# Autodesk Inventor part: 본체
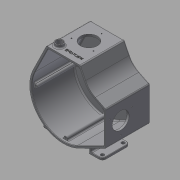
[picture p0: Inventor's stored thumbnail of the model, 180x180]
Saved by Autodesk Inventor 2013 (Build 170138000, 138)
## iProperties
Created: 2017-05
Part Number: 본체
Material: 일반
Document SubType Name: Modeling
Designer: mduedu
Density: 1 g/cm^3
Author: mduedu
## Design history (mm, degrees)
sketch "스케치1"
  geometry: L1 (-71.801, 35.28)-(-40, 100); L2 (-40, 100)-(40, 100); L3 (40, 100)-(59.768, 59.768); L4 (59.768, 59.768)-(100, 40); L5 (100, 40)-(100, -40); L6 (100, -40)-(35.28, -71.801); A1 r 80 centre (0, 0) between (-71.801, 35.28) and (35.28, -71.801); 3 further points
  constraints: 12 end point, 4 tangent, 2 midpoint, 2 point on circle, 1 centre point, 1 coincident, 1 horizontal, 1 horizontal alignment, 1 perpendicular, 1 vertical alignment
  dimensions: "d0" = 160 diameter of A1; "d2" = 100 distance from line of L2 point (0, 0); "d3" = 100 distance from line of L5 point (0, 0); "d4" = 80 distance of L1.end L2.end; "d5" = 80 distance of L4.end L5.end
extrude "돌출1" new body sketch "스케치1" distance "d6" = 5; taper "d7" = 0 deg
fillet "모깎기1" dims "d8" = 50
sketch "스케치2"
  geometry: C1 r 22 at (0, 0); 1 further point
  constraints: 1 centre point, 1 coincident
  dimensions: "d9" = 44 diameter of C1
extrude "돌출2" join sketch "스케치2" distance "d10" = 22.5; taper "d11" = 0 deg
sketch "스케치3"
  geometry: C1 r 18.5 at (0, 0); 1 further point
  constraints: 1 centre point, 1 coincident
  dimensions: "d12" = 37 diameter of C1
extrude "돌출3" cut sketch "스케치3" distance "d13" = 9; taper "d14" = 0 deg
fillet "모깎기2" dims "d15" = 3
sketch "스케치4"
  geometry: L1 (35.28, -71.801)-(100, -40) reference; L2 (100, -40)-(100, 40) reference; L3 (100, 40)-(75.073, 52.248) reference; L4 (52.248, 75.073)-(40, 100) reference; L5 (40, 100)-(-40, 100) reference; L6 (-40, 100)-(-71.801, 35.28) reference; L7 (-36.886, 95)-(36.886, 95); L8 (36.886, 95)-(47.76, 72.868); L9 (72.868, 47.76)-(95, 36.886); L10 (95, 36.886)-(95, -36.886); L11 (95, -36.886)-(33.075, -67.313); L12 (-67.313, 33.075)-(-36.886, 95); C1 r 25 at (0, 0) reference; A1 r 50 centre (97.123, 97.123) between (52.248, 75.073) and (75.073, 52.248) reference; A2 r 80 centre (0, 0) between (-71.801, 35.28) and (35.28, -71.801) reference; A3 r 55 centre (97.123, 97.123) between (47.76, 72.868) and (72.868, 47.76); A4 r 75 centre (0, 0) between (-67.313, 33.075) and (33.075, -67.313); 1 further point
  constraints: 12 end point, 4 point on circle, 2 centre point, 7 other
  dimensions: "d16" = 5 distance between parallel lines of L7 L5
extrude "돌출4" join sketch "스케치4" distance "d17" = 100; taper "d18" = 0 deg
sketch "스케치5"
  geometry: L1 (80, 0)-(0, 0) reference; C1 r 20 at (40, -45); 2 further points
  constraints: 1 centre point, 1 midpoint, 1 vertical alignment
  dimensions: "d19" = 40 diameter of C1; "d21" = 45 distance from line of C1.centre L1
extrude "돌출5" cut sketch "스케치5" stored distance "d22" = 100; taper "d23" = 0 deg
sketch "스케치6"
  geometry: L1 (0, 0)-(0, -105) reference; L2 (80, -105)-(0, -105) reference; C1 r 9 at (14, -89); 1 further point
  constraints: 1 centre point
  dimensions: "d24" = 18 diameter of C1; "d26" = 14 distance from line of C1.centre L1; "d27" = 16 distance from line of C1.centre L2
extrude "돌출6" join sketch "스케치6" distance "d28" = 7; taper "d29" = 0 deg
hole "구멍1" diameter "d32" = 14; stored, may be unused: countersink angle "d36" = 90 deg, drill point angle "d38" = 118 deg; dims "d33" = 6, "d34" = 4, "d35" = 2, "d37" = 8, "d39" = 10, "d40" = 10
sketch "스케치7"
  geometry: L1 (-105, 0)-(-105, 80) reference; L2 (0, 0)-(0, 80) reference; C1 r 20 at (-70, 40); 2 further points
  constraints: 1 centre point, 1 horizontal alignment, 1 midpoint
  dimensions: "d41" = 40 diameter of C1; "d42" = 35 distance from line of C1.centre L1
extrude "돌출7" cut sketch "스케치7" stored distance "d43" = 7; taper "d44" = 0 deg
node "작업 평면1"
sketch "스케치8"
  geometry: L1 (47.76, 72.868)-(36.886, 95) reference; L2 (36.886, 95)-(-36.886, 95) reference; L3 (-36.886, 95)-(-67.313, 33.075) reference; L4 (33.075, -67.313)-(95, -36.886) reference; L5 (95, -36.886)-(95, 36.886) reference; L6 (95, 36.886)-(72.868, 47.76) reference; L7 (95, 36.886)-(95, -36.886) reference; L8 (-36.886, 95)-(36.886, 95) reference; L9 (36.886, 95)-(47.76, 72.868) reference; L10 (-71, 4)-(-74.893, 4); L11 (-71, -4)-(-74.893, -4); L12 (-4, -71)-(-4, -74.893); L13 (4, -71)-(4, -74.893); L14 (30.394, 91)-(30.394, 95); L15 (34.394, 87)-(40.817, 87); L16 (30.394, 95)-(36.886, 95); L17 (36.886, 95)-(37.984, 92.764); L18 (91, 30.394)-(95, 30.394); L19 (87, 34.394)-(87, 40.817); L20 (87, 40.817)-(95, 36.886); L21 (95, 36.886)-(95, 30.394); C1 r 25 at (0, 0) reference; A1 r 75 centre (0, 0) between (-67.313, 33.075) and (33.075, -67.313) reference; A2 r 55 centre (97.123, 97.123) between (47.76, 72.868) and (72.868, 47.76) reference; A3 r 4 centre (-71, 0) between (-71, 4) and (-71, -4); A4 r 4 centre (0, -71) between (-4, -71) and (4, -71); A5 r 4 centre (34.394, 91) between (30.394, 91) and (34.394, 87); A6 r 75 centre (0, 0) between (-67.313, 33.075) and (33.075, -67.313) reference; A7 r 4 centre (91, 34.394) between (91, 30.394) and (87, 34.394); 1 further point
  constraints: 24 end point, 17 point on circle, 14 tangent, 5 point on line, 4 centre point, 3 equal radius, 3 perpendicular, 3 vertical, 2 collinear, 2 horizontal, 1 horizontal alignment, 1 parallel, 1 vertical alignment
  dimensions: "d46" = 8 diameter of A3
extrude "돌출8" join sketch "스케치8" stored distance "d49" = 7; taper "d50" = 0 deg
node "작업 평면2"
sketch "스케치9"
  geometry: L1 (71.801, 0)-(71.801, 105) reference; L2 (71.801, 0)-(-35.28, 0) reference; L3 (-35.28, 0)-(-35.28, 105) reference; L4 (71.801, 105)-(-35.28, 105) reference; L5 (40, 0)-(40, 105) reference; L6 (71.801, 52.5)-(-35.28, 52.5); L7 (71.801, 20)-(40, 20); L8 (40, 20)-(40, 85); L9 (40, 85)-(71.801, 85); L10 (71.801, 85)-(71.801, 20); 1 further point
  constraints: 10 end point, 2 midpoint, 2 parallel, 2 point on line, 1 horizontal, 1 perpendicular, 1 other
  dimensions: "d52" = 20 distance between parallel lines of L7 L2
extrude "돌출9" join sketch "스케치9" distance "d53" = 5; taper "d54" = 0 deg
fillet "모깎기3" dims "d55" = 8
sketch "스케치10"
  geometry: C1 r 4 at (-63.801, -28); C2 r 4 at (-63.801, -77); A1 r 8 centre (-63.801, -28) between (-63.801, -20) and (-71.801, -28) reference; A2 r 8 centre (-63.801, -77) between (-71.801, -77) and (-63.801, -85) reference; 1 further point
  constraints: 2 centre point, 2 coincident, 1 equal radius
  dimensions: "d56" = 8 diameter of C1
extrude "돌출10" cut sketch "스케치10" stored distance "d57" = 50.5; taper "d58" = 0 deg
sketch "스케치11"
  geometry: L1 (-63.801, -20)-(-40, -20) reference; L2 (-40, -20)-(-40, -85) reference; L3 (-40, -85)-(-63.801, -85) reference; L4 (-71.801, -77)-(-71.801, -28) reference; L5 (71.801, -77)-(71.801, -28) reference; L6 (40, -85)-(63.801, -85) reference; L7 (40, -20)-(40, -85) reference; L8 (63.801, -20)-(40, -20) reference; L9 (-40, -85)-(-45, -85); L10 (-45, -85)-(-45, -20); L11 (-45, -20)-(-40, -20); L12 (-40, -20)-(-40, -85); L13 (40, -85)-(45, -85); L14 (45, -85)-(45, -20); L15 (45, -20)-(40, -20); L16 (40, -20)-(40, -85); C1 r 4 at (-63.801, -28) reference; C2 r 4 at (-63.801, -77) reference; C3 r 4 at (63.801, -28) reference; C4 r 4 at (63.801, -77) reference; A1 r 8 centre (-63.801, -28) between (-63.801, -20) and (-71.801, -28) reference; A2 r 8 centre (-63.801, -77) between (-71.801, -77) and (-63.801, -85) reference; A3 r 8 centre (63.801, -28) between (71.801, -28) and (63.801, -20) reference; A4 r 8 centre (63.801, -77) between (63.801, -85) and (71.801, -77) reference; 1 further point
  constraints: 16 end point, 4 parallel, 2 horizontal, 2 perpendicular, 2 point on line
  dimensions: "d59" = 5 distance of L10.end L11.end; "d61" = 5 distance of L14.end L15.end
extrude "돌출11" join sketch "스케치11" stored distance "d62" = 5; taper "d63" = 0 deg
fillet "모깎기4" dims "d64" = 3
fillet "모깎기5" dims "d65" = 1
fillet "모깎기6" dims "d66" = 1
fillet "모깎기8" dims "d68" = 1
fillet "모깎기9" dims "d70" = 3, "d101" = 1
fillet "모깎기10" dims "d71" = 3
fillet "모깎기11" dims "d72" = 3
fillet "모깎기12" dims "d73" = 3
fillet "모깎기13" dims "d76" = 3
chamfer "모따기1" distance "d77" = 0.5; stored, may be unused: second distance "d78" = 2, angle "d79" = 45 deg
sketch "스케치13"
  geometry: L1 (76.263, 0)-(0, 0) reference; 2 further points
  constraints: 1 other
  dimensions: "d83" = 15 distance from line of point (48.131, 15) L1; "d84" = 10 horizontal distance of point (48.131, 15) point (38.131, 105)
feature "엠보싱1" sketch "스케치13" dims "d0" = 160, "d2" = 100, "d3" = 100, "d4" = 80, "d5" = 80, "d85" = 0.5, "d86" = 0
chamfer "모따기2" distance "d87" = 1; stored, may be unused: second distance "d88" = 2, angle "d89" = 45 deg
chamfer "모따기3" distance "d90" = 1; stored, may be unused: second distance "d91" = 2, angle "d92" = 45 deg
sketch "스케치14"
  geometry: 3 further points
  constraints: 3 other
hole "구멍2" sketch "스케치14" at (-55.375, -40), (-3.414, -40), (-29.394, -85) diameter "d93" = 2.459; stored, may be unused: countersink angle "d97" = 90 deg, drill point angle "d99" = 0 deg; dims "d94" = 6, "d95" = 4, "d96" = 2, "d98" = 8
sketch "스케치15"
  geometry: 3 further points
  constraints: 3 other
hole "구멍4" sketch "스케치15" at (-55.981, -14.394), (-4.019, -14.394), (-30, -59.394) diameter "d102" = 2.459; stored, may be unused: countersink angle "d106" = 90 deg, drill point angle "d108" = 0 deg; dims "d103" = 6, "d104" = 4, "d105" = 2, "d107" = 8
sketch "스케치16"
  geometry: 4 further points
  constraints: 4 other
hole "구멍6" sketch "스케치16" at (0, -71), (91, 34.394), (34.394, 91), (-71, 0) diameter "d109" = 2.459; stored, may be unused: countersink angle "d113" = 90 deg, drill point angle "d115" = 120 deg; dims "d110" = 8.5, "d111" = 4, "d112" = 2, "d114" = 10
node "솔리드1"
mirror "대칭1"
node "투영된 루프1"
node "투영된 루프2"
node "투영된 루프3"
node "투영된 루프4"
node "투영된 루프5"
other parameters: "d45" = 95
